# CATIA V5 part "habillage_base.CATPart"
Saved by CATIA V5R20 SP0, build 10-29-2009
Part number: habillage_base
Bounding box of the stored display mesh (mm): x -50.742 to 149.258, y -310 to 290, z -253 to 10
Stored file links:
  C:\Users\Noëllie\Documents\IFMA\2A\S3\IAO\Projet Artobolevski\Catia\habillage_base.CATPart
  C:\Users\Noëllie\Documents\IFMA\2A\S3\IAO\Projet Artobolevski\Catia\assemblage_balance.CATProduct
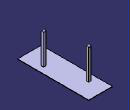
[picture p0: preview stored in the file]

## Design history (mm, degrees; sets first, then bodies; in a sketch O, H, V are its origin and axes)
Set1
  Point1 "b_2": linked copy from another document
  Point2 "A2": linked copy from another document
  Plane1 "Plan_base1": linked copy from another document
  Point3 "b_1": linked copy from another document
  Point4 "A1": linked copy from another document
  Plane2 "Plan_socle": linked copy from another document
Body1 (main body)
  Sketch1 on yz-plane, origin (0, 0, 0), H (0, 1, 0), V (0, 0, 1)
    line L1 (140, 0) -> (140, -250)
    point P1 (140, 0)
    line L2 (160, 0) -> (160, -250)
    line L3 (140, -250) -> (160, -250)
    arc A1 centre (150, 0) radius 10 from (140, 0) to (160, 0) cw
    point P5 (150, 0)
    reference projected point E1 (150, -250) from Point1
    reference projected point E2 (150, 0) from Point2
    distance L1 L2 = 20
    coincidence: P1 H, E1 L3, P5 E2
    vertical: L1 V, L2 V
    horizontal: L3 H
    tangency: A1 L2
  Pad1: profile Sketch1, direction (1, 0, 0), length 20
  Sketch2 on Plane1, origin (100, 0, 0), H (0, 1, 0), V (0, 0, 1)
    line L1 (-160, 0) -> (-160, -250)
    line L2 (-140, 0) -> (-140, -250)
    line L3 (-160, -250) -> (-140, -250)
    point P5 (-150, 0)
    reference projected point E1 (-150, -250) from Point3
    arc A1 centre (-150, 0) radius 10 from (-160, 0) to (-140, 0) cw
    point P6 (-150, 0)
    reference projected point E2 (-150, 0) from Point4
    vertical: L1 V, L2 V
    horizontal: L3 H
    coincidence: P5 H, E1 L3, P6 E2
    tangency: A1 L2
  Pad2: profile Sketch2, direction (1, 0, 0), length 0, opposite side length 20
  Sketch3 on Plane2, origin (0, 0, -250), H (1, 0, 0), V (0, 1, 0)
    line L1 (-50.7417, 290) -> (149.2583, 290)
    line L2 (149.2583, 290) -> (149.2583, -310)
    line L3 (149.2583, -310) -> (-50.7417, -310)
    line L4 (-50.7417, -310) -> (-50.7417, 290)
    distance L1 L3 = 600
    length L1 = 200
    horizontal: L1 H, L3 H
    vertical: L2 V, L4 V
  Pad3: profile Sketch3, direction (0, 0, 1), length 0, opposite side length 3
